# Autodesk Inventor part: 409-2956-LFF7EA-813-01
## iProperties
Created: 2010-11
Part Number: 409-2956-LFF7EA-813-01
Material: 3/8" OD TUBE - SS
Description: PT TUBING
Document SubType Name: Modeling
Designer: S. Boerckel
Engineer: Steve Boerckel
Mass: 970.103 g
Surface Area: 2101.43 cm^2
Volume: 120.062 cm^3
Density: 8.08 g/cm^3
Length: 156.546 in
Author: S. Boerckel
Revision Number: 0
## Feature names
1. Sweep1
2. Sweep2
